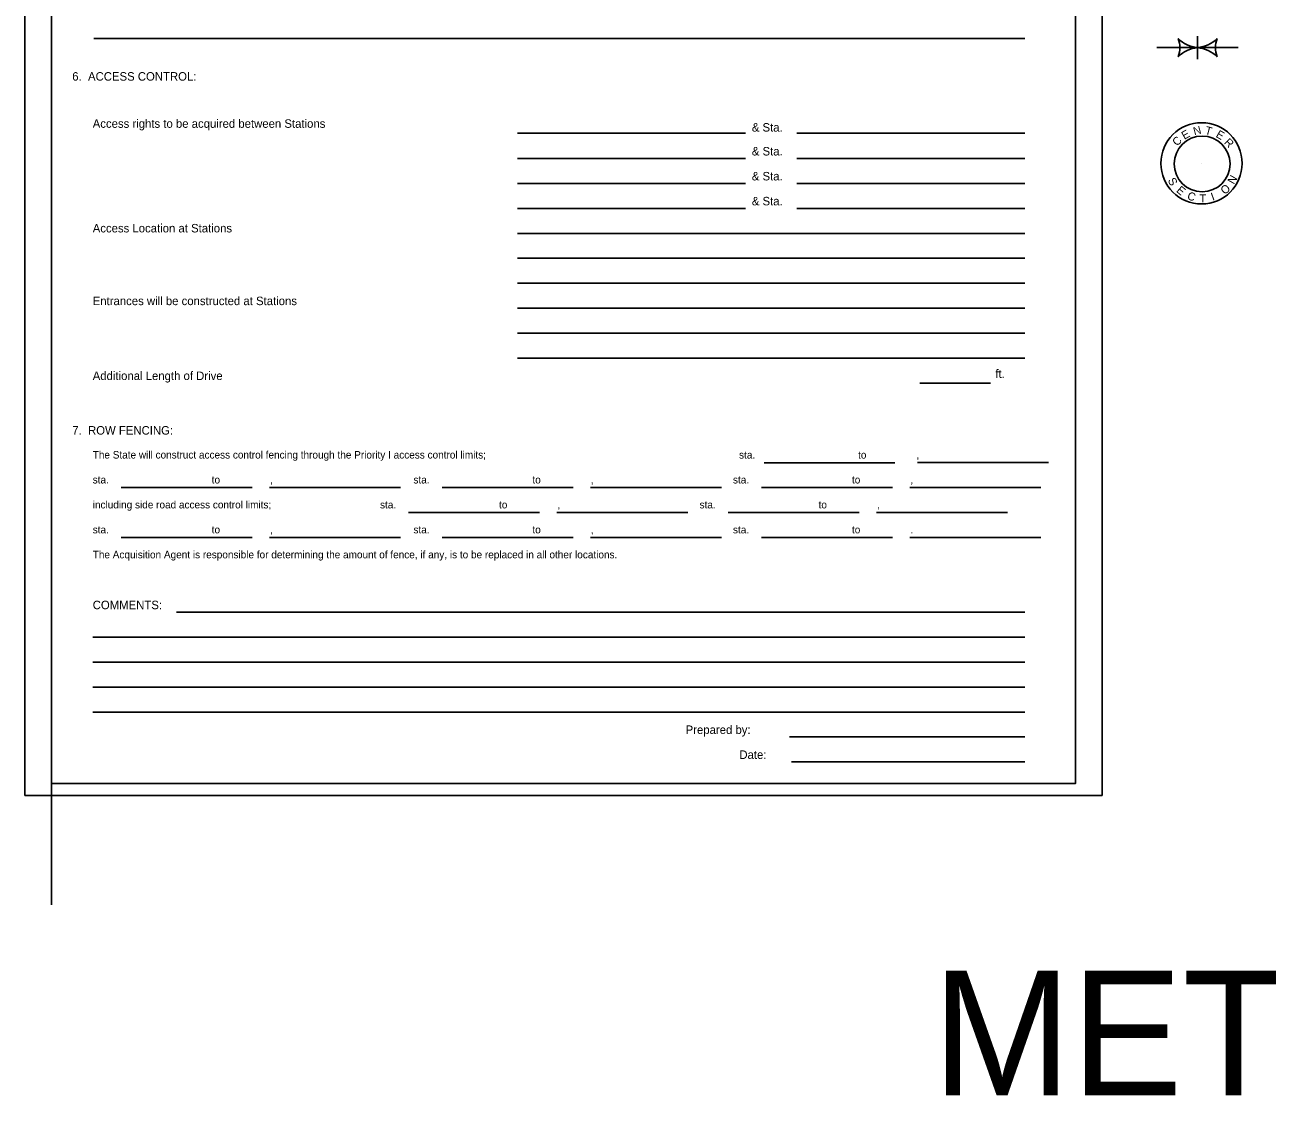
# Model space of a CAD drawing. Extents: x -64422 to -63705, y -154995 to -154568.
# Drawn here: x -64421.9 to -64175.4, y -154994.8 to -154782 of the extents above; entities that cross this region are included whole.
import ezdxf

# ---------------------------------------------------------------- set-up
doc = ezdxf.new("R2010")
doc.units = 0
for name, color, linetype in [('Level 16', 7, 'Continuous'), ('rowdsnPSConstructPlot', 7, 'Continuous'), ('rowdsnPSSummary', 7, 'Continuous'), ('rowdsnPSText', 7, 'Continuous'), ('rowdsnSymbolsPL', 7, 'Continuous')]:
    doc.layers.add(name, color=color, linetype=linetype)

msp = doc.modelspace()

# ---------------------------------------------------------------- linework, layer by layer
at = {"layer": 'Level 16'}
msp.add_line((-64188.41, -154809.45), (-64188.41, -154809.45), dxfattribs=at)
for centre, radius in [((-64188.41, -154809.45), 8.06), ((-64188.29, -154809.57), 5.54)]:
    msp.add_circle(centre, radius, dxfattribs=at)
at = {"layer": 'rowdsnPSConstructPlot'}
msp.add_lwpolyline([(-64213.43, -154592.36), (-64416.63, -154592.36), (-64416.63, -154932.55), (-64213.43, -154932.55)], close=True, dxfattribs=at)
at = {"layer": 'rowdsnPSSummary'}
for p, q in [((-64421.91, -154934.87), (-64421.91, -154582.8)), ((-64208.15, -154582.8), (-64208.15, -154934.87)), ((-64223.47, -154784.68), (-64408.2, -154784.68)), ((-64278.9, -154803.45), (-64324.15, -154803.45)), ((-64223.47, -154803.45), (-64268.72, -154803.45)), ((-64278.9, -154808.5), (-64324.15, -154808.5)), ((-64223.47, -154808.5), (-64268.72, -154808.5)), ((-64278.9, -154813.45), (-64324.15, -154813.45)), ((-64223.47, -154813.45), (-64268.72, -154813.45)), ((-64278.9, -154818.4), (-64324.15, -154818.4)), ((-64223.47, -154818.4), (-64268.72, -154818.4)), ((-64223.47, -154823.39), (-64324.15, -154823.39)), ((-64223.47, -154828.3), (-64324.15, -154828.3)), ((-64223.47, -154833.25), (-64324.15, -154833.25)), ((-64223.47, -154838.2), (-64324.15, -154838.2)), ((-64223.47, -154843.15), (-64324.15, -154843.15)), ((-64223.47, -154848.1), (-64324.15, -154848.1)), ((-64230.26, -154853.05), (-64244.31, -154853.05)), ((-64249.24, -154868.86), (-64275.23, -154868.86)), ((-64218.77, -154868.85), (-64244.76, -154868.85)), ((-64376.78, -154873.79), (-64402.77, -154873.79)), ((-64347.34, -154873.79), (-64373.33, -154873.79)), ((-64313.13, -154873.79), (-64339.12, -154873.79)), ((-64283.69, -154873.79), (-64309.68, -154873.79)), ((-64249.72, -154873.79), (-64275.71, -154873.79)), ((-64220.29, -154873.79), (-64246.28, -154873.79)), ((-64319.77, -154878.74), (-64345.76, -154878.74)), ((-64290.33, -154878.74), (-64316.32, -154878.74)), ((-64256.36, -154878.74), (-64282.35, -154878.74)), ((-64226.92, -154878.74), (-64252.91, -154878.74)), ((-64376.78, -154883.69), (-64402.77, -154883.69)), ((-64347.34, -154883.69), (-64373.33, -154883.69)), ((-64313.13, -154883.69), (-64339.12, -154883.69)), ((-64283.69, -154883.69), (-64309.68, -154883.69)), ((-64249.72, -154883.69), (-64275.71, -154883.69)), ((-64220.29, -154883.69), (-64246.28, -154883.69)), ((-64223.47, -154898.54), (-64391.84, -154898.54)), ((-64223.47, -154903.49), (-64408.44, -154903.49)), ((-64223.47, -154908.44), (-64408.44, -154908.44)), ((-64223.47, -154913.39), (-64408.44, -154913.39)), ((-64223.47, -154918.34), (-64408.44, -154918.34)), ((-64223.47, -154923.29), (-64270.17, -154923.29)), ((-64223.47, -154928.24), (-64269.77, -154928.24)), ((-64416.63, -154932.55), (-64416.63, -154956.6)), ((-64416.63, -154932.55), (-64416.63, -154956.6)), ((-64208.15, -154934.87), (-64421.91, -154934.87))]:
    msp.add_line(p, q, dxfattribs=at)
at = {"layer": 'rowdsnSymbolsPL'}
for p, q in [((-64189.19, -154788.78), (-64189.19, -154784.2)), ((-64189.19, -154786.49), (-64197.26, -154786.49)), ((-64189.19, -154786.49), (-64181.11, -154786.49))]:
    msp.add_line(p, q, dxfattribs=at)
for centre, radius, start, end in [((-64188.49, -154779.94), 6.59, 226.0869, 263.8941), ((-64197.85, -154786.49), 5.13, 339.3932, 20.6068), ((-64189.89, -154779.94), 6.59, 276.1059, 313.9131), ((-64180.52, -154786.49), 5.13, 159.3932, 200.6068), ((-64188.49, -154793.04), 6.59, 96.1059, 133.9131), ((-64189.89, -154793.04), 6.59, 46.0869, 83.8941)]:
    msp.add_arc(centre, radius, start, end, dxfattribs=at)

# ---------------------------------------------------------------- texts
at = {"layer": 'Level 16'}
for s, rotation, p in [('E', 29.9995, (-64191.81, -154804.79)), ('N', 15.0017, (-64189.82, -154803.91)), ('T', 344.9983, (-64187.84, -154803.6)), ('E', 330.0026, (-64185.7, -154804.15)), ('C', 45, (-64193.26, -154806.14)), ('R', 315, (-64184.05, -154805.41)), ('S', 299.9995, (-64195.18, -154812.85)), ('N', 60.0042, (-64181.98, -154813.74)), ('E', 320.0014, (-64193.53, -154815.01)), ('C', 340.0006, (-64191.39, -154816.51)), ('I', 19.9994, (-64186.21, -154816.91)), ('O', 39.9986, (-64183.81, -154815.74))]:
    msp.add_text(s, height=1.61, rotation=rotation, dxfattribs=at).set_placement(p)
msp.add_text('T', height=1.61, dxfattribs=at).set_placement((-64188.81, -154817.2))
at = {"layer": 'rowdsnPSSummary'}
for s, height, p in [('6.  ACCESS CONTROL:', 1.6832, (-64412.5, -154793.04)), ('Access rights to be acquired between Stations', 1.6832, (-64408.44, -154802.4)), ('& Sta.', 1.683, (-64277.65, -154803.15)), ('& Sta.', 1.683, (-64277.65, -154807.89)), ('& Sta.', 1.683, (-64277.65, -154812.84)), ('& Sta.', 1.683, (-64277.65, -154817.79)), ('Access Location at Stations', 1.6832, (-64408.44, -154823.16)), ('Entrances will be constructed at Stations', 1.6832, (-64408.44, -154837.59)), ('Additional Length of Drive', 1.6832, (-64408.44, -154852.45)), ('ft.', 1.683, (-64229.32, -154852.03)), ('7.  ROW FENCING:', 1.6832, (-64412.5, -154863.28)), ('The State will construct access control fencing through the Priority I access control limits; ', 1.4851, (-64408.44, -154868.03)), ('sta.                                     to                  ,', 1.4851, (-64280.18, -154868.04)), ('sta.                                     to                  ,', 1.4851, (-64408.44, -154872.98)), ('sta.                                     to                  ,', 1.4851, (-64344.8, -154872.98)), ('sta.                                     to                  ,', 1.4851, (-64281.39, -154872.98)), ('including side road access control limits; ', 1.4851, (-64408.44, -154877.93)), ('sta.                                     to                  ,', 1.4851, (-64351.43, -154877.93)), ('sta.                                     to                  ,', 1.4851, (-64288.02, -154877.93)), ('sta.                                     to                  ,', 1.4851, (-64408.44, -154882.88)), ('sta.                                     to                  ,', 1.4851, (-64344.8, -154882.88)), ('sta.                                     to                  .', 1.4851, (-64281.39, -154882.88)), ('The Acquisition Agent is responsible for determining the amount of fence, if any, is to be replaced in all other locations.', 1.48515, (-64408.44, -154887.83)), ('COMMENTS:', 1.683, (-64408.44, -154897.93)), ('Prepared by:', 1.6832, (-64290.78, -154922.69)), ('Date:', 1.683, (-64280.12, -154927.64))]:
    msp.add_text(s, height=height, dxfattribs=at).set_placement(p)
at = {"layer": 'rowdsnPSText'}
msp.add_text('METRIC PLOT PLAN & SUMMARY', height=24.7525, dxfattribs=at).set_placement((-64241.82, -154994.41))

doc.saveas('drawing.dxf')
